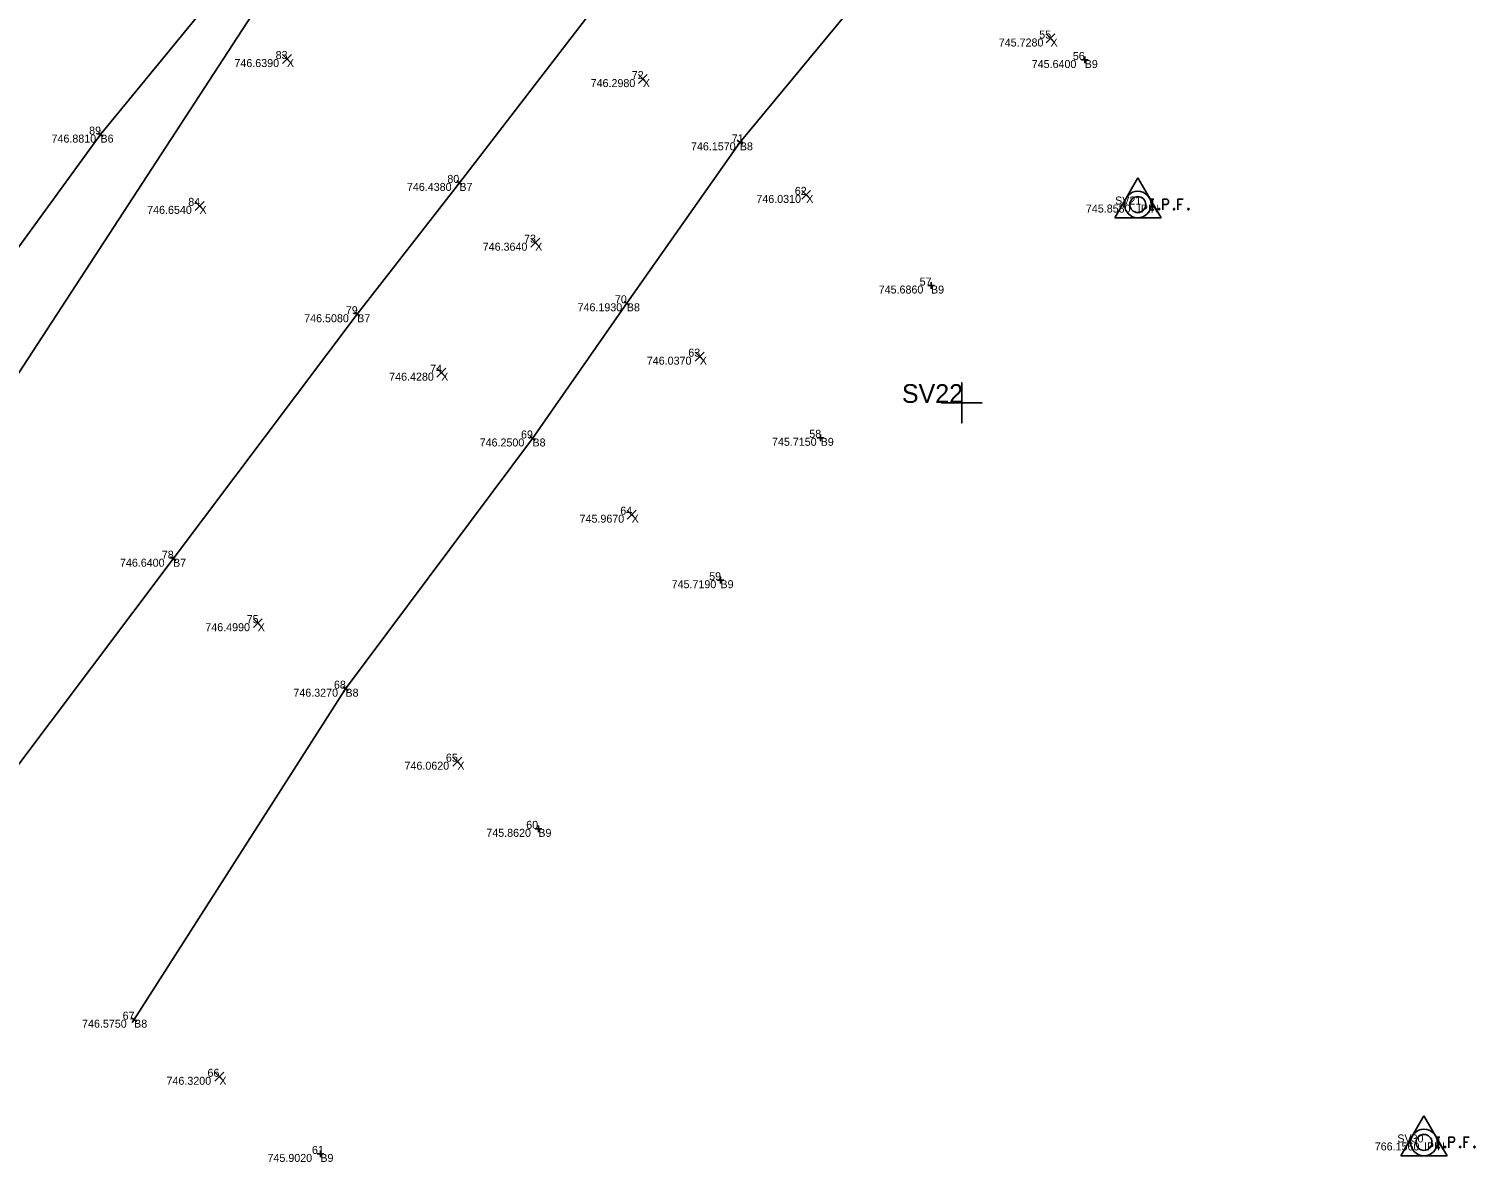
# Model space of a CAD drawing. Extents: x 1857337 to 1857837, y 693958 to 694371.
# Drawn here: x 1857723.4 to 1857831.8, y 694146.6 to 694231.5 of the extents above; entities that cross this region are included whole.
import ezdxf

# ---------------------------------------------------------------- set-up
doc = ezdxf.new("R2010")
doc.units = 0
for name, color, linetype in [('BR_X_SV_Pier_Cap_Bottom', 7, 'Continuous'), ('DR_X_Cells', 7, 'Continuous'), ('GK_Drainage_Nodes', 7, 'Continuous'), ('SV_X_Shot_Marker', 7, 'Continuous'), ('SV_X_Text_Comment', 7, 'Continuous'), ('SV_X_Text_Description', 7, 'Continuous'), ('SV_X_Text_Elevation', 7, 'Continuous'), ('SV_X_Text_Name', 7, 'Continuous'), ('UT_X_Electric_Cells', 7, 'Continuous')]:
    doc.layers.add(name, color=color, linetype=linetype)

msp = doc.modelspace()

# ---------------------------------------------------------------- linework, layer by layer
at = {"layer": 'BR_X_SV_Pier_Cap_Bottom'}
for p, q in [((1857802.51, 694229.41), (1857802.51, 694228.91)), ((1857802.26, 694229.16), (1857802.76, 694229.16)), ((1857802.51, 694229.16), (1857802.51, 694229.16)), ((1857728.53, 694223.71), (1857728.94, 694223.42)), ((1857728.59, 694223.36), (1857728.88, 694223.77)), ((1857728.74, 694223.57), (1857728.74, 694223.57)), ((1857776.85, 694222.83), (1857776.47, 694223.15)), ((1857776.82, 694223.18), (1857776.5, 694222.8)), ((1857776.66, 694222.99), (1857776.66, 694222.99)), ((1857755.83, 694219.8), (1857755.44, 694220.11)), ((1857755.79, 694220.15), (1857755.48, 694219.76)), ((1857755.64, 694219.95), (1857755.64, 694219.95)), ((1857790.74, 694212.26), (1857791.24, 694212.26)), ((1857790.99, 694212.51), (1857790.99, 694212.01)), ((1857790.99, 694212.26), (1857790.99, 694212.26)), ((1857768.39, 694210.79), (1857767.99, 694211.07)), ((1857768.33, 694211.14), (1857768.05, 694210.73)), ((1857748.17, 694209.96), (1857747.78, 694210.26)), ((1857748.13, 694210.31), (1857747.82, 694209.91)), ((1857747.98, 694210.11), (1857747.98, 694210.11)), ((1857768.19, 694210.93), (1857768.19, 694210.93)), ((1857761.32, 694200.66), (1857760.91, 694200.95)), ((1857761.26, 694201.01), (1857760.98, 694200.6)), ((1857761.12, 694200.8), (1857761.12, 694200.8)), ((1857782.47, 694200.85), (1857782.97, 694200.85)), ((1857782.72, 694201.1), (1857782.72, 694200.6)), ((1857782.72, 694200.85), (1857782.72, 694200.85)), ((1857734.38, 694191.64), (1857733.98, 694191.94)), ((1857734.33, 694191.99), (1857734.03, 694191.59)), ((1857734.18, 694191.79), (1857734.18, 694191.79)), ((1857775.21, 694190.43), (1857775.21, 694189.93)), ((1857774.96, 694190.18), (1857775.46, 694190.18)), ((1857775.21, 694190.18), (1857775.21, 694190.18)), ((1857747.3, 694181.9), (1857746.9, 694182.2)), ((1857747.25, 694182.25), (1857746.95, 694181.85)), ((1857747.1, 694182.05), (1857747.1, 694182.05)), ((1857761.31, 694171.55), (1857761.81, 694171.55)), ((1857761.56, 694171.8), (1857761.56, 694171.3)), ((1857761.56, 694171.55), (1857761.56, 694171.55)), ((1857731.47, 694157.12), (1857731.05, 694157.39)), ((1857731.39, 694157.46), (1857731.12, 694157.04)), ((1857731.26, 694157.25), (1857731.26, 694157.25)), ((1857744.97, 694147.19), (1857745.47, 694147.19)), ((1857745.22, 694147.44), (1857745.22, 694146.94)), ((1857745.22, 694147.19), (1857745.22, 694147.19))]:
    msp.add_line(p, q, dxfattribs=at)
at = {"layer": 'DR_X_Cells'}
for points in [[(1857807.5, 694218.73), (1857807.68, 694218.73)], [(1857807.59, 694217.93), (1857807.59, 694218.73)], [(1857808.37, 694217.93), (1857808.37, 694218.73), (1857808.64, 694218.73), (1857808.66, 694218.73), (1857808.7, 694218.72), (1857808.72, 694218.7), (1857808.74, 694218.69), (1857808.76, 694218.66), (1857808.77, 694218.63), (1857808.79, 694218.58), (1857808.79, 694218.5), (1857808.78, 694218.48), (1857808.77, 694218.44), (1857808.75, 694218.39), (1857808.72, 694218.37), (1857808.71, 694218.36), (1857808.68, 694218.35), (1857808.64, 694218.34), (1857808.37, 694218.34)], [(1857809.88, 694218.73), (1857809.5, 694218.73), (1857809.5, 694217.93)], [(1857807.5, 694217.93), (1857807.68, 694217.93)], [(1857808.07, 694218.04), (1857808.1, 694218.04), (1857808.11, 694218.03), (1857808.13, 694218), (1857808.13, 694217.97), (1857808.11, 694217.95), (1857808.1, 694217.93), (1857808.07, 694217.93), (1857808.05, 694217.95), (1857808.04, 694217.97), (1857808.04, 694218), (1857808.05, 694218.03), (1857808.07, 694218.04)], [(1857809.19, 694218.04), (1857809.22, 694218.04), (1857809.24, 694218.03), (1857809.25, 694218), (1857809.25, 694217.97), (1857809.24, 694217.95), (1857809.22, 694217.93), (1857809.19, 694217.93), (1857809.18, 694217.95), (1857809.16, 694217.97), (1857809.16, 694218), (1857809.18, 694218.03), (1857809.19, 694218.04)], [(1857809.5, 694218.34), (1857809.77, 694218.34)], [(1857810.27, 694218.04), (1857810.3, 694218.04), (1857810.31, 694218.03), (1857810.33, 694218), (1857810.33, 694217.97), (1857810.31, 694217.95), (1857810.3, 694217.93), (1857810.27, 694217.93), (1857810.25, 694217.95), (1857810.23, 694217.97), (1857810.23, 694218), (1857810.25, 694218.03), (1857810.27, 694218.04)], [(1857828.94, 694148.45), (1857829.12, 694148.45)], [(1857829.03, 694147.65), (1857829.03, 694148.45)], [(1857829.81, 694147.65), (1857829.81, 694148.45), (1857830.08, 694148.45), (1857830.11, 694148.45), (1857830.14, 694148.44), (1857830.16, 694148.42), (1857830.18, 694148.41), (1857830.2, 694148.38), (1857830.22, 694148.35), (1857830.23, 694148.3), (1857830.23, 694148.22), (1857830.22, 694148.2), (1857830.21, 694148.16), (1857830.19, 694148.11), (1857830.17, 694148.09), (1857830.15, 694148.08), (1857830.12, 694148.07), (1857830.08, 694148.06), (1857829.81, 694148.06)], [(1857831.32, 694148.45), (1857830.94, 694148.45), (1857830.94, 694147.65)], [(1857828.94, 694147.65), (1857829.12, 694147.65)], [(1857829.51, 694147.76), (1857829.54, 694147.76), (1857829.55, 694147.75), (1857829.57, 694147.72), (1857829.57, 694147.69), (1857829.55, 694147.67), (1857829.54, 694147.65), (1857829.51, 694147.65), (1857829.49, 694147.67), (1857829.48, 694147.69), (1857829.48, 694147.72), (1857829.49, 694147.75), (1857829.51, 694147.76)], [(1857830.63, 694147.76), (1857830.66, 694147.76), (1857830.68, 694147.75), (1857830.69, 694147.72), (1857830.69, 694147.69), (1857830.68, 694147.67), (1857830.66, 694147.65), (1857830.63, 694147.65), (1857830.62, 694147.67), (1857830.6, 694147.69), (1857830.6, 694147.72), (1857830.62, 694147.75), (1857830.63, 694147.76)], [(1857830.94, 694148.06), (1857831.21, 694148.06)], [(1857831.71, 694147.76), (1857831.74, 694147.76), (1857831.75, 694147.75), (1857831.77, 694147.72), (1857831.77, 694147.69), (1857831.75, 694147.67), (1857831.74, 694147.65), (1857831.71, 694147.65), (1857831.69, 694147.67), (1857831.68, 694147.69), (1857831.68, 694147.72), (1857831.69, 694147.75), (1857831.71, 694147.76)]]:
    msp.add_lwpolyline(points, dxfattribs=at)
for centre in [(1857806.49, 694218.33), (1857827.94, 694148.05)]:
    msp.add_circle(centre, 0.6, dxfattribs=at)
at = {"layer": 'GK_Drainage_Nodes'}
for p, q in [((1857804.76, 694217.33), (1857806.49, 694220.33)), ((1857806.49, 694220.33), (1857808.23, 694217.33)), ((1857806.49, 694218.33), (1857806.49, 694218.33)), ((1857808.23, 694217.33), (1857804.76, 694217.33)), ((1857826.2, 694147.05), (1857827.94, 694150.05)), ((1857827.94, 694150.05), (1857829.67, 694147.05)), ((1857829.67, 694147.05), (1857826.2, 694147.05)), ((1857827.94, 694148.05), (1857827.94, 694148.05))]:
    msp.add_line(p, q, dxfattribs=at)
for centre in [(1857806.49, 694218.33), (1857827.94, 694148.05)]:
    msp.add_circle(centre, 1, dxfattribs=at)
at = {"layer": 'SV_X_Shot_Marker'}
msp.add_line((1857793.3, 694203.47), (1857793.3, 694203.47), dxfattribs=at)
msp.add_lwpolyline([(1857793.3, 694203.47), (1857793.3, 694204.97), (1857793.3, 694203.47), (1857791.8, 694203.47), (1857793.3, 694203.47), (1857793.3, 694201.97), (1857793.3, 694203.47), (1857794.8, 694203.47)], close=True, dxfattribs=at)
at = {"layer": 'SV_X_Text_Elevation'}
for p, q in [((1857799.61, 694230.44), (1857800.28, 694231.11)), ((1857799.61, 694231.11), (1857800.28, 694230.44)), ((1857742.38, 694228.9), (1857743.05, 694229.56)), ((1857742.38, 694229.56), (1857743.05, 694228.9)), ((1857769.06, 694227.4), (1857769.72, 694228.07)), ((1857769.06, 694228.07), (1857769.72, 694227.4)), ((1857781.3, 694218.72), (1857781.97, 694219.38)), ((1857781.3, 694219.38), (1857781.97, 694218.72)), ((1857735.83, 694217.89), (1857736.5, 694218.56)), ((1857735.83, 694218.56), (1857736.5, 694217.89)), ((1857760.99, 694215.14), (1857761.66, 694215.81)), ((1857760.99, 694215.81), (1857761.66, 694215.14)), ((1857773.32, 694206.59), (1857773.99, 694207.26)), ((1857773.32, 694207.26), (1857773.99, 694206.59)), ((1857753.95, 694205.39), (1857754.62, 694206.06)), ((1857753.95, 694206.06), (1857754.62, 694205.39)), ((1857768.22, 694194.76), (1857768.89, 694195.42)), ((1857768.22, 694195.42), (1857768.89, 694194.76)), ((1857740.2, 694186.63), (1857740.87, 694187.29)), ((1857740.2, 694187.29), (1857740.87, 694186.63)), ((1857755.16, 694176.25), (1857755.82, 694176.92)), ((1857755.16, 694176.92), (1857755.82, 694176.25)), ((1857737.32, 694152.64), (1857737.98, 694153.31)), ((1857737.32, 694153.31), (1857737.98, 694152.64))]:
    msp.add_line(p, q, dxfattribs=at)
at = {"layer": 'UT_X_Electric_Cells'}
for points in [[(1857789.96, 694304.6), (1857771.69, 694278.3), (1857757.22, 694258.85), (1857703.3, 694176.12), (1857697.07, 694181.68), (1857715.68, 694205.65), (1857728.74, 694223.57), (1857737.21, 694233.91), (1857746.66, 694246.32)], [(1857810.28, 694291.03), (1857789.92, 694262.4), (1857775.4, 694247.35), (1857765.09, 694232.21), (1857755.64, 694219.95), (1857747.98, 694210.11), (1857734.18, 694191.79), (1857715.87, 694167.45)], [(1857823.2, 694284.34), (1857800.6, 694253.24), (1857789.06, 694237.97), (1857776.66, 694222.99), (1857768.19, 694210.93), (1857761.12, 694200.8), (1857747.1, 694182.05), (1857731.26, 694157.25)]]:
    msp.add_lwpolyline(points, dxfattribs=at)

# ---------------------------------------------------------------- texts
at = {"layer": 'SV_X_Shot_Marker'}
msp.add_text('SV22', height=1.4, dxfattribs=at).set_placement((1857788.81, 694203.47))
at = {"layer": 'SV_X_Text_Comment'}
for s, p in [('X', (1857799.95, 694230.17)), ('X', (1857742.71, 694228.63)), ('B9', (1857802.51, 694228.56)), ('X', (1857769.39, 694227.13)), ('B6', (1857728.74, 694222.97)), ('B8', (1857776.66, 694222.39)), ('B7', (1857755.64, 694219.35)), ('X', (1857781.64, 694218.45)), ('X', (1857736.16, 694217.63)), ('IPIN', (1857806.49, 694217.73)), ('X', (1857761.32, 694214.87)), ('B9', (1857790.99, 694211.66)), ('B7', (1857747.98, 694209.51)), ('B8', (1857768.19, 694210.33)), ('X', (1857773.66, 694206.33)), ('X', (1857754.28, 694205.13)), ('B8', (1857761.12, 694200.2)), ('B9', (1857782.72, 694200.25)), ('X', (1857768.55, 694194.49)), ('B7', (1857734.18, 694191.19)), ('B9', (1857775.21, 694189.58)), ('X', (1857740.53, 694186.36)), ('B8', (1857747.1, 694181.45)), ('X', (1857755.49, 694175.98)), ('B9', (1857761.56, 694170.95)), ('B8', (1857731.26, 694156.65)), ('X', (1857737.65, 694152.37)), ('B9', (1857745.22, 694146.59)), ('IPIN', (1857827.94, 694147.45))]:
    msp.add_text(s, height=0.6, dxfattribs=at).set_placement(p)
at = {"layer": 'SV_X_Text_Description'}
for s, p in [('745.7280', (1857796.07, 694230.17)), ('746.6390', (1857738.78, 694228.63)), ('745.6400', (1857798.54, 694228.56)), ('746.2980', (1857765.48, 694227.13)), ('746.8810', (1857725.07, 694222.97)), ('746.1570', (1857773, 694222.39)), ('746.4380', (1857751.71, 694219.35)), ('746.0310', (1857777.9, 694218.45)), ('746.6540', (1857732.24, 694217.63)), ('745.8580', (1857802.6, 694217.73)), ('746.3640', (1857757.39, 694214.87)), ('745.6860', (1857787.07, 694211.66)), ('746.5080', (1857744.01, 694209.51)), ('746.1930', (1857764.5, 694210.33)), ('746.0370', (1857769.69, 694206.33)), ('746.4280', (1857750.38, 694205.13)), ('746.2500', (1857757.16, 694200.2)), ('745.7150', (1857779.07, 694200.25)), ('745.9670', (1857764.65, 694194.49)), ('746.6400', (1857730.2, 694191.19)), ('745.7190', (1857771.55, 694189.58)), ('746.4990', (1857736.6, 694186.36)), ('746.3270', (1857743.2, 694181.45)), ('746.0620', (1857751.53, 694175.98)), ('745.8620', (1857757.66, 694170.95)), ('746.5750', (1857727.36, 694156.65)), ('746.3200', (1857733.69, 694152.37)), ('745.9020', (1857741.26, 694146.59)), ('766.1560', (1857824.25, 694147.45))]:
    msp.add_text(s, height=0.6, dxfattribs=at).set_placement(p)
at = {"layer": 'SV_X_Text_Name'}
for s, p in [('55', (1857799.1, 694230.77)), ('83', (1857741.87, 694229.23)), ('56', (1857801.62, 694229.16)), ('72', (1857768.56, 694227.73)), ('89', (1857727.89, 694223.57)), ('71', (1857776.05, 694222.99)), ('80', (1857754.74, 694219.95)), ('62', (1857780.78, 694219.05)), ('84', (1857735.32, 694218.23)), ('SV21', (1857804.79, 694218.33)), ('73', (1857760.49, 694215.47)), ('57', (1857790.14, 694212.26)), ('70', (1857767.3, 694210.93)), ('79', (1857747.13, 694210.11)), ('63', (1857772.8, 694206.93)), ('74', (1857753.45, 694205.73)), ('69', (1857760.26, 694200.8)), ('58', (1857781.87, 694200.85)), ('64', (1857767.7, 694195.09)), ('78', (1857733.34, 694191.79)), ('59', (1857774.36, 694190.18)), ('75', (1857739.7, 694186.96)), ('68', (1857746.24, 694182.05)), ('65', (1857754.63, 694176.58)), ('60', (1857760.65, 694171.55)), ('67', (1857730.4, 694157.25)), ('66', (1857736.76, 694152.97)), ('SV30', (1857825.94, 694148.05)), ('61', (1857744.59, 694147.19))]:
    msp.add_text(s, height=0.6, dxfattribs=at).set_placement(p)

doc.saveas('drawing.dxf')
